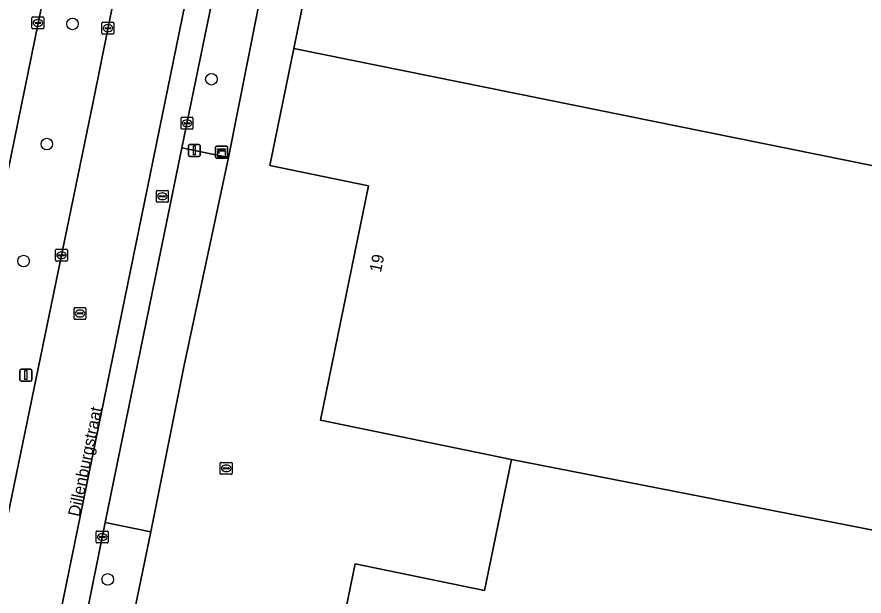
# Model space of a CAD drawing. Extents: x 157692 to 159674, y 381452 to 383291.
# Drawn here: x 158535.7 to 158606.9, y 382160.6 to 382209.3 of the extents above; entities that cross this region are included whole.
import ezdxf

# ---------------------------------------------------------------- set-up
doc = ezdxf.new("R2010")
doc.units = 0
for name, color, linetype in [('IMGEO_Berm_groen', 7, 'Continuous'), ('IMGEO_Boom', 7, 'Continuous'), ('IMGEO_Erf', 7, 'Continuous'), ('IMGEO_Kast', 7, 'Continuous'), ('IMGEO_Kolk', 7, 'Continuous'), ('IMGEO_Lichtmast', 7, 'Continuous'), ('IMGEO_Openbare_ruimte_label', 7, 'Continuous'), ('IMGEO_Pand', 7, 'Continuous'), ('IMGEO_Pand_nummerreeks', 7, 'Continuous'), ('IMGEO_Rijbaan_lokaal_gesloten', 7, 'Continuous'), ('IMGEO_Rijbaan_lokaal_open', 7, 'Continuous'), ('IMGEO_Rioolput', 7, 'Continuous'), ('IMGEO_Voetpad_open', 7, 'Continuous')]:
    doc.layers.add(name, color=color, linetype=linetype)

msp = doc.modelspace()

# ---------------------------------------------------------------- linework, layer by layer
at = {"layer": 'IMGEO_Berm_groen'}
for points in [[(158566.644, 382322.187), (158567.234, 382325.064), (158567.304, 382325.746), (158567.225, 382326.384), (158567.068, 382326.86), (158566.787, 382327.371), (158566.493, 382327.735), (158566.011, 382328.143), (158565.497, 382328.42), (158565.051, 382328.557), (158564.939, 382328.591), (158564.425, 382328.647), (158563.854, 382328.604), (158563.281, 382328.442), (158562.742, 382328.162), (158562.266, 382327.772), (158561.897, 382327.314), (158561.609, 382326.746), (158561.45, 382326.139), (158553.124, 382285.066), (158549.349, 382267.06), (158522.982, 382137.975)], [(158528.747, 382136.998), (158534.877, 382167.21), (158542.075, 382202.135), (158547.202, 382227.455), (158566.644, 382322.187)]]:
    msp.add_lwpolyline(points, dxfattribs=at)
at = {"layer": 'IMGEO_Boom'}
for centre in [(158540.349, 382208.695), (158552.041, 382204.045), (158538.189, 382198.589), (158536.234, 382188.746), (158543.31, 382161.961)]:
    msp.add_circle(centre, 0.489, dxfattribs=at)
at = {"layer": 'IMGEO_Erf'}
msp.add_lwpolyline([(158556.642, 382213.448), (158553.461, 382197.47), (158549.725, 382179.858), (158546.937, 382165.963), (158540.709, 382135.881), (158546.509, 382134.668), (158563.223, 382131.236), (158563.315, 382131.7), (158554.772, 382133.456), (158554.818, 382133.659), (158556.568, 382133.298), (158557.225, 382136.428), (158558.548, 382136.172), (158564.131, 382163.272), (158575.023, 382161.028), (158577.294, 382172.047), (158561.216, 382175.361), (158565.247, 382195.087), (158556.948, 382196.783), (158558.961, 382206.635), (158560.882, 382216.032)], dxfattribs=at)
at = {"layer": 'IMGEO_Kast'}
for p, q in [((158552.387, 382197.476), (158552.387, 382198.317)), ((158552.387, 382198.317), (158552.387, 382197.476)), ((158552.462, 382198.401), (158553.303, 382198.401)), ((158553.303, 382198.401), (158552.462, 382198.401)), ((158553.387, 382198.326), (158553.387, 382197.485)), ((158553.387, 382197.485), (158553.387, 382198.326)), ((158553.312, 382197.401), (158552.471, 382197.401)), ((158552.471, 382197.401), (158553.312, 382197.401))]:
    msp.add_line(p, q, dxfattribs=at)
for points in [[(158552.582, 382198.191), (158553.182, 382198.191), (158553.182, 382198.106), (158552.582, 382198.106), (158552.582, 382198.191)], [(158552.582, 382198.016), (158553.182, 382198.016), (158553.182, 382197.527), (158552.582, 382197.527), (158552.582, 382198.016)]]:
    msp.add_lwpolyline(points, dxfattribs=at)
msp.add_circle((158552.666, 382197.865), 0.0377, dxfattribs=at)
for centre, start, end in [((158552.465, 382198.323), 92.4484, 184.28452), ((158552.465, 382198.323), 92.4484, 184.28452), ((158553.309, 382198.323), 2.4484, 94.28452), ((158553.309, 382198.323), 2.4484, 94.28452), ((158552.465, 382197.479), 182.4484, 274.28452), ((158552.465, 382197.479), 182.4484, 274.28452), ((158553.309, 382197.479), 272.4484, 4.28452), ((158553.309, 382197.479), 272.4484, 4.28452)]:
    msp.add_arc(centre, 0.0779, start, end, dxfattribs=at)
at = {"layer": 'IMGEO_Kolk'}
for p, q in [((158536.939, 382208.356), (158536.939, 382209.208)), ((158537.014, 382209.282), (158537.866, 382209.282)), ((158537.94, 382209.208), (158537.94, 382208.356)), ((158537.198, 382208.776), (158537.198, 382208.788)), ((158537.636, 382208.739), (158537.238, 382208.739)), ((158537.241, 382208.825), (158537.639, 382208.825)), ((158537.45, 382208.502), (158537.425, 382208.502)), ((158537.427, 382209.062), (158537.452, 382209.062)), ((158537.682, 382208.788), (158537.682, 382208.776)), ((158542.83, 382207.91), (158542.83, 382208.762)), ((158542.905, 382208.836), (158543.757, 382208.836)), ((158543.318, 382208.616), (158543.343, 382208.616)), ((158543.831, 382208.762), (158543.831, 382207.91)), ((158537.866, 382208.282), (158537.014, 382208.282)), ((158543.757, 382207.836), (158542.905, 382207.836)), ((158543.089, 382208.33), (158543.089, 382208.342)), ((158543.527, 382208.293), (158543.129, 382208.293)), ((158543.132, 382208.379), (158543.53, 382208.379)), ((158543.341, 382208.056), (158543.316, 382208.056)), ((158543.573, 382208.342), (158543.573, 382208.33)), ((158549.485, 382199.911), (158549.485, 382200.763)), ((158549.56, 382200.837), (158550.412, 382200.837)), ((158549.973, 382200.617), (158549.998, 382200.617)), ((158550.486, 382200.763), (158550.486, 382199.911)), ((158549.744, 382200.331), (158549.744, 382200.343)), ((158550.182, 382200.294), (158549.784, 382200.294)), ((158549.787, 382200.38), (158550.185, 382200.38)), ((158549.996, 382200.057), (158549.971, 382200.057)), ((158550.228, 382200.343), (158550.228, 382200.331)), ((158550.412, 382199.837), (158549.56, 382199.837)), ((158538.922, 382188.807), (158538.922, 382189.659)), ((158538.997, 382189.733), (158539.849, 382189.733)), ((158539.181, 382189.227), (158539.181, 382189.239)), ((158539.619, 382189.19), (158539.221, 382189.19)), ((158539.224, 382189.276), (158539.622, 382189.276)), ((158539.41, 382189.513), (158539.435, 382189.513)), ((158539.665, 382189.239), (158539.665, 382189.227)), ((158539.923, 382189.659), (158539.923, 382188.807)), ((158539.849, 382188.733), (158538.997, 382188.733)), ((158539.433, 382188.953), (158539.408, 382188.953)), ((158552.783, 382170.882), (158552.783, 382171.734)), ((158552.858, 382171.808), (158553.71, 382171.808)), ((158553.271, 382171.588), (158553.296, 382171.588)), ((158553.784, 382171.734), (158553.784, 382170.882)), ((158553.71, 382170.808), (158552.858, 382170.808)), ((158553.042, 382171.302), (158553.042, 382171.314)), ((158553.48, 382171.265), (158553.082, 382171.265)), ((158553.085, 382171.351), (158553.483, 382171.351)), ((158553.294, 382171.028), (158553.269, 382171.028)), ((158553.526, 382171.314), (158553.526, 382171.302)), ((158542.351, 382165.104), (158542.351, 382165.956)), ((158542.426, 382166.03), (158543.278, 382166.03)), ((158542.839, 382165.81), (158542.864, 382165.81)), ((158543.352, 382165.956), (158543.352, 382165.104)), ((158543.278, 382165.03), (158542.426, 382165.03)), ((158542.61, 382165.524), (158542.61, 382165.536)), ((158543.048, 382165.487), (158542.65, 382165.487)), ((158542.653, 382165.573), (158543.051, 382165.573)), ((158542.862, 382165.25), (158542.837, 382165.25)), ((158543.094, 382165.536), (158543.094, 382165.524))]:
    msp.add_line(p, q, dxfattribs=at)
for points in [[(158536.939, 382208.356), (158536.939, 382209.208)], [(158537.014, 382209.282), (158537.866, 382209.282)], [(158537.94, 382209.208), (158537.94, 382208.356)], [(158542.83, 382207.91), (158542.83, 382208.762)], [(158542.905, 382208.836), (158543.757, 382208.836)], [(158543.831, 382208.762), (158543.831, 382207.91)], [(158537.866, 382208.282), (158537.014, 382208.282)], [(158543.757, 382207.836), (158542.905, 382207.836)], [(158549.485, 382199.911), (158549.485, 382200.763)], [(158549.56, 382200.837), (158550.412, 382200.837)], [(158550.486, 382200.763), (158550.486, 382199.911)], [(158550.412, 382199.837), (158549.56, 382199.837)], [(158538.922, 382188.807), (158538.922, 382189.659)], [(158538.997, 382189.733), (158539.849, 382189.733)], [(158539.923, 382189.659), (158539.923, 382188.807)], [(158539.849, 382188.733), (158538.997, 382188.733)], [(158552.783, 382170.882), (158552.783, 382171.734)], [(158552.858, 382171.808), (158553.71, 382171.808)], [(158553.784, 382171.734), (158553.784, 382170.882)], [(158553.71, 382170.808), (158552.858, 382170.808)], [(158542.351, 382165.104), (158542.351, 382165.956)], [(158542.426, 382166.03), (158543.278, 382166.03)], [(158543.352, 382165.956), (158543.352, 382165.104)], [(158543.278, 382165.03), (158542.426, 382165.03)]]:
    msp.add_lwpolyline(points, dxfattribs=at)
for centre, radius, start, end in [((158537.016, 382209.206), 0.0765, 91.55205, 178.44795), ((158537.016, 382209.206), 0.0765, 91.55205, 178.44795), ((158537.864, 382209.206), 0.0765, 1.55205, 88.44795), ((158537.864, 382209.206), 0.0765, 1.55205, 88.44795), ((158537.238, 382208.785), 0.0403, 85.87752, 175.75265), ((158537.235, 382208.775), 0.0366, 178.93798, 274.71019), ((158537.639, 382208.782), 0.043, 264.86636, 352.45326), ((158537.643, 382208.787), 0.0386, 1.73085, 96.63898), ((158542.907, 382208.76), 0.0765, 91.55205, 178.44795), ((158542.907, 382208.76), 0.0765, 91.55205, 178.44795), ((158543.755, 382208.76), 0.0765, 1.55205, 88.44795), ((158543.755, 382208.76), 0.0765, 1.55205, 88.44795), ((158537.016, 382208.358), 0.0765, 181.55205, 268.44795), ((158537.016, 382208.358), 0.0765, 181.55205, 268.44795), ((158537.864, 382208.358), 0.0765, 271.55205, 358.44795), ((158537.864, 382208.358), 0.0765, 271.55205, 358.44795), ((158542.907, 382207.912), 0.0765, 181.55205, 268.44795), ((158542.907, 382207.912), 0.0765, 181.55205, 268.44795), ((158543.129, 382208.339), 0.0403, 85.87752, 175.75265), ((158543.126, 382208.329), 0.0366, 178.93798, 274.71019), ((158543.53, 382208.336), 0.043, 264.86636, 352.45326), ((158543.534, 382208.341), 0.0386, 1.73085, 96.63898), ((158543.755, 382207.912), 0.0765, 271.55205, 358.44795), ((158543.755, 382207.912), 0.0765, 271.55205, 358.44795), ((158549.562, 382200.761), 0.0765, 91.55205, 178.44795), ((158549.562, 382200.761), 0.0765, 91.55205, 178.44795), ((158550.41, 382200.761), 0.0765, 1.55205, 88.44795), ((158550.41, 382200.761), 0.0765, 1.55205, 88.44795), ((158549.562, 382199.913), 0.0765, 181.55205, 268.44795), ((158549.562, 382199.913), 0.0765, 181.55205, 268.44795), ((158549.784, 382200.34), 0.0403, 85.87752, 175.75265), ((158549.781, 382200.33), 0.0366, 178.93798, 274.71019), ((158550.185, 382200.337), 0.043, 264.86636, 352.45326), ((158550.189, 382200.342), 0.0386, 1.73085, 96.63898), ((158550.41, 382199.913), 0.0765, 271.55205, 358.44795), ((158550.41, 382199.913), 0.0765, 271.55205, 358.44795), ((158538.999, 382189.657), 0.0765, 91.55205, 178.44795), ((158538.999, 382189.657), 0.0765, 91.55205, 178.44795), ((158539.221, 382189.236), 0.0403, 85.87752, 175.75265), ((158539.218, 382189.226), 0.0366, 178.93798, 274.71019), ((158539.622, 382189.233), 0.043, 264.86636, 352.45326), ((158539.626, 382189.238), 0.0386, 1.73085, 96.63898), ((158539.847, 382189.657), 0.0765, 1.55205, 88.44795), ((158539.847, 382189.657), 0.0765, 1.55205, 88.44795), ((158538.999, 382188.809), 0.0765, 181.55205, 268.44795), ((158538.999, 382188.809), 0.0765, 181.55205, 268.44795), ((158539.847, 382188.809), 0.0765, 271.55205, 358.44795), ((158539.847, 382188.809), 0.0765, 271.55205, 358.44795), ((158552.86, 382171.732), 0.0765, 91.55205, 178.44795), ((158552.86, 382171.732), 0.0765, 91.55205, 178.44795), ((158553.708, 382171.732), 0.0765, 1.55205, 88.44795), ((158553.708, 382171.732), 0.0765, 1.55205, 88.44795), ((158552.86, 382170.884), 0.0765, 181.55205, 268.44795), ((158552.86, 382170.884), 0.0765, 181.55205, 268.44795), ((158553.082, 382171.311), 0.0403, 85.87752, 175.75265), ((158553.079, 382171.301), 0.0366, 178.93798, 274.71019), ((158553.483, 382171.308), 0.043, 264.86636, 352.45326), ((158553.487, 382171.313), 0.0386, 1.73085, 96.63898), ((158553.708, 382170.884), 0.0765, 271.55205, 358.44795), ((158553.708, 382170.884), 0.0765, 271.55205, 358.44795), ((158542.428, 382165.954), 0.0765, 91.55205, 178.44795), ((158542.428, 382165.954), 0.0765, 91.55205, 178.44795), ((158543.276, 382165.954), 0.0765, 1.55205, 88.44795), ((158543.276, 382165.954), 0.0765, 1.55205, 88.44795), ((158542.428, 382165.106), 0.0765, 181.55205, 268.44795), ((158542.428, 382165.106), 0.0765, 181.55205, 268.44795), ((158542.65, 382165.533), 0.0403, 85.87752, 175.75265), ((158542.647, 382165.523), 0.0366, 178.93798, 274.71019), ((158543.051, 382165.53), 0.043, 264.86636, 352.45326), ((158543.055, 382165.535), 0.0386, 1.73085, 96.63898), ((158543.276, 382165.106), 0.0765, 271.55205, 358.44795), ((158543.276, 382165.106), 0.0765, 271.55205, 358.44795)]:
    msp.add_arc(centre, radius, start, end, dxfattribs=at)
for centre, major_axis, ratio, start_param, end_param in [((158537.426, 382208.782), (-0.387, 0.002), 0.722429, 4.712389, 7.853982), ((158537.451, 382208.782), (-0.39, 0.002), 0.717154, 1.570796, 4.712389), ((158543.317, 382208.336), (-0.387, 0.002), 0.722429, 4.712389, 7.853982), ((158543.342, 382208.336), (-0.39, 0.002), 0.717154, 1.570796, 4.712389), ((158549.972, 382200.337), (-0.387, 0.002), 0.722429, 4.712389, 7.853982), ((158549.997, 382200.337), (-0.39, 0.002), 0.717154, 1.570796, 4.712389), ((158539.409, 382189.233), (-0.387, 0.002), 0.722429, 4.712389, 7.853982), ((158539.434, 382189.233), (-0.39, 0.002), 0.717154, 1.570796, 4.712389), ((158553.27, 382171.308), (-0.387, 0.002), 0.722429, 4.712389, 7.853982), ((158553.295, 382171.308), (-0.39, 0.002), 0.717154, 1.570796, 4.712389), ((158542.838, 382165.53), (-0.387, 0.002), 0.722429, 4.712389, 7.853982), ((158542.863, 382165.53), (-0.39, 0.002), 0.717154, 1.570796, 4.712389)]:
    msp.add_ellipse(centre, major_axis=major_axis, ratio=ratio, start_param=start_param, end_param=end_param, dxfattribs=at)
at = {"layer": 'IMGEO_Lichtmast'}
for p, q in [((158550.102, 382197.654), (158550.102, 382198.454)), ((158550.102, 382198.454), (158550.102, 382197.654)), ((158550.202, 382198.554), (158550.992, 382198.554)), ((158550.992, 382198.554), (158550.202, 382198.554)), ((158551.092, 382198.454), (158551.092, 382197.654)), ((158551.092, 382197.654), (158551.092, 382198.454)), ((158550.992, 382197.554), (158550.202, 382197.554)), ((158550.202, 382197.554), (158550.992, 382197.554)), ((158535.931, 382178.75), (158535.931, 382179.55)), ((158535.931, 382179.55), (158535.931, 382178.75)), ((158536.031, 382179.65), (158536.821, 382179.65)), ((158536.821, 382179.65), (158536.031, 382179.65)), ((158536.921, 382179.55), (158536.921, 382178.75)), ((158536.921, 382178.75), (158536.921, 382179.55)), ((158536.821, 382178.65), (158536.031, 382178.65)), ((158536.031, 382178.65), (158536.821, 382178.65))]:
    msp.add_line(p, q, dxfattribs=at)
for points in [[(158550.522, 382198.429), (158550.672, 382198.429), (158550.672, 382197.679), (158550.522, 382197.679), (158550.522, 382198.429)], [(158536.351, 382179.525), (158536.501, 382179.525), (158536.501, 382178.775), (158536.351, 382178.775), (158536.351, 382179.525)]]:
    msp.add_lwpolyline(points, dxfattribs=at)
for centre, start, end in [((158550.202, 382198.454), 90, 180), ((158550.202, 382198.454), 90, 180), ((158550.992, 382198.454), 0, 90), ((158550.992, 382198.454), 360, 90), ((158550.202, 382197.654), 180, 270), ((158550.202, 382197.654), 180, 270), ((158550.992, 382197.654), 270, 0), ((158550.992, 382197.654), 270, 0), ((158536.031, 382179.55), 90, 180), ((158536.031, 382179.55), 90, 180), ((158536.821, 382179.55), 0, 90), ((158536.821, 382179.55), 360, 90), ((158536.031, 382178.75), 180, 270), ((158536.031, 382178.75), 180, 270), ((158536.821, 382178.75), 270, 0), ((158536.821, 382178.75), 270, 0)]:
    msp.add_arc(centre, 0.1, start, end, dxfattribs=at)
at = {"layer": 'IMGEO_Pand'}
for points in [[(158576.115, 382230.619), (158575.584, 382228.145), (158575.263, 382228.214), (158574.032, 382222.478), (158571.367, 382223.019), (158571.578, 382224.05), (158562.884, 382225.827), (158561.639, 382219.733), (158563.119, 382219.432), (158562.364, 382215.729), (158560.882, 382216.032), (158558.961, 382206.635), (158623.952, 382193.477), (158624.324, 382195.285), (158629.34, 382219.832), (158581.016, 382229.628)], [(158623.952, 382193.477), (158558.961, 382206.635), (158556.948, 382196.783), (158565.247, 382195.087), (158561.216, 382175.361), (158577.294, 382172.047), (158617.909, 382164.108)], [(158617.909, 382164.108), (158577.294, 382172.047), (158575.023, 382161.028), (158564.131, 382163.272), (158558.548, 382136.172), (158557.225, 382136.428), (158556.568, 382133.298), (158554.818, 382133.659), (158554.772, 382133.456), (158563.315, 382131.7), (158563.223, 382131.236), (158573.743, 382129.079), (158604.33, 382122.808), (158609.261, 382121.797)]]:
    msp.add_lwpolyline(points, close=True, dxfattribs=at)
at = {"layer": 'IMGEO_Rijbaan_lokaal_gesloten'}
for points in [[(158566.717, 382304.975), (158570.119, 382321.454), (158566.644, 382322.187), (158547.202, 382227.455), (158542.075, 382202.135), (158534.877, 382167.21), (158528.747, 382136.998), (158534.64, 382136.161), (158544.988, 382186.707), (158554.178, 382231.666)], [(158563.237, 382275.98), (158554.178, 382231.666), (158544.988, 382186.707), (158534.64, 382136.161), (158536.85, 382135.847), (158537.008, 382136.63), (158543.098, 382166.746), (158549.561, 382198.266), (158555.39, 382226.63), (158560.201, 382250.104)], [(158522.982, 382137.975), (158549.349, 382267.06)]]:
    msp.add_lwpolyline(points, dxfattribs=at)
at = {"layer": 'IMGEO_Rijbaan_lokaal_open'}
msp.add_lwpolyline([(158546.937, 382165.963), (158549.725, 382179.858), (158553.461, 382197.47), (158549.561, 382198.266), (158543.098, 382166.746)], close=True, dxfattribs=at)
at = {"layer": 'IMGEO_Rioolput'}
for p, q in [((158547.41, 382193.766), (158547.41, 382194.618)), ((158547.485, 382194.692), (158548.337, 382194.692)), ((158547.669, 382194.186), (158547.669, 382194.198)), ((158547.712, 382194.235), (158548.11, 382194.235)), ((158547.898, 382194.472), (158547.923, 382194.472)), ((158548.153, 382194.198), (158548.153, 382194.186)), ((158548.411, 382194.618), (158548.411, 382193.766)), ((158548.337, 382193.692), (158547.485, 382193.692)), ((158548.107, 382194.149), (158547.709, 382194.149)), ((158547.921, 382193.912), (158547.896, 382193.912)), ((158540.475, 382183.91), (158540.475, 382184.762)), ((158540.55, 382184.836), (158541.402, 382184.836)), ((158540.734, 382184.33), (158540.734, 382184.342)), ((158541.172, 382184.293), (158540.774, 382184.293)), ((158540.777, 382184.379), (158541.175, 382184.379)), ((158540.963, 382184.616), (158540.988, 382184.616)), ((158541.218, 382184.342), (158541.218, 382184.33)), ((158541.476, 382184.762), (158541.476, 382183.91)), ((158541.402, 382183.836), (158540.55, 382183.836)), ((158540.986, 382184.056), (158540.961, 382184.056))]:
    msp.add_line(p, q, dxfattribs=at)
for points in [[(158547.41, 382193.766), (158547.41, 382194.618)], [(158547.485, 382194.692), (158548.337, 382194.692)], [(158548.411, 382194.618), (158548.411, 382193.766)], [(158548.337, 382193.692), (158547.485, 382193.692)], [(158540.475, 382183.91), (158540.475, 382184.762)], [(158540.55, 382184.836), (158541.402, 382184.836)], [(158541.476, 382184.762), (158541.476, 382183.91)], [(158541.402, 382183.836), (158540.55, 382183.836)]]:
    msp.add_lwpolyline(points, dxfattribs=at)
for centre, radius, start, end in [((158547.487, 382194.616), 0.0765, 91.55205, 178.44795), ((158547.487, 382194.616), 0.0765, 91.55205, 178.44795), ((158547.709, 382194.195), 0.0403, 85.87752, 175.75265), ((158547.706, 382194.185), 0.0366, 178.93798, 274.71019), ((158548.11, 382194.192), 0.043, 264.86636, 352.45326), ((158548.114, 382194.197), 0.0386, 1.73085, 96.63898), ((158548.335, 382194.616), 0.0765, 1.55205, 88.44795), ((158548.335, 382194.616), 0.0765, 1.55205, 88.44795), ((158547.487, 382193.768), 0.0765, 181.55205, 268.44795), ((158547.487, 382193.768), 0.0765, 181.55205, 268.44795), ((158548.335, 382193.768), 0.0765, 271.55205, 358.44795), ((158548.335, 382193.768), 0.0765, 271.55205, 358.44795), ((158540.552, 382184.76), 0.0765, 91.55205, 178.44795), ((158540.552, 382184.76), 0.0765, 91.55205, 178.44795), ((158540.774, 382184.339), 0.0403, 85.87752, 175.75265), ((158540.771, 382184.329), 0.0366, 178.93798, 274.71019), ((158541.175, 382184.336), 0.043, 264.86636, 352.45326), ((158541.179, 382184.341), 0.0386, 1.73085, 96.63898), ((158541.4, 382184.76), 0.0765, 1.55205, 88.44795), ((158541.4, 382184.76), 0.0765, 1.55205, 88.44795), ((158540.552, 382183.912), 0.0765, 181.55205, 268.44795), ((158540.552, 382183.912), 0.0765, 181.55205, 268.44795), ((158541.4, 382183.912), 0.0765, 271.55205, 358.44795), ((158541.4, 382183.912), 0.0765, 271.55205, 358.44795)]:
    msp.add_arc(centre, radius, start, end, dxfattribs=at)
for centre, major_axis, ratio, start_param, end_param in [((158547.897, 382194.192), (-0.387, 0.002), 0.722429, 4.712389, 7.853982), ((158547.922, 382194.192), (-0.39, 0.002), 0.717154, 1.570796, 4.712389), ((158540.962, 382184.336), (-0.387, 0.002), 0.722429, 4.712389, 7.853982), ((158540.987, 382184.336), (-0.39, 0.002), 0.717154, 1.570796, 4.712389)]:
    msp.add_ellipse(centre, major_axis=major_axis, ratio=ratio, start_param=start_param, end_param=end_param, dxfattribs=at)
at = {"layer": 'IMGEO_Voetpad_open'}
for points in [[(158549.561, 382198.266), (158553.461, 382197.47), (158556.642, 382213.448), (158559.221, 382225.883), (158555.39, 382226.63)], [(158546.937, 382165.963), (158543.098, 382166.746), (158537.008, 382136.63), (158540.709, 382135.881)]]:
    msp.add_lwpolyline(points, close=True, dxfattribs=at)

# ---------------------------------------------------------------- texts
at = {"layer": 'IMGEO_Openbare_ruimte_label'}
msp.add_text('Dillenburgstraat', height=1, rotation=78.28547, dxfattribs=at).set_placement((158540.938, 382167.192))
at = {"layer": 'IMGEO_Pand_nummerreeks'}
msp.add_text('19', height=1, rotation=78.44938, dxfattribs=at).set_placement((158566.297, 382187.741))

doc.saveas('drawing.dxf')
